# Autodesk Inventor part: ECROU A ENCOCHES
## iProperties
Created: 2004-11
Part Number: ECROU A ENCOCHES
Document SubType Name: Modeling
Designer: Bruno
Manufacturer: Standard
Standards Organization: Custom
Author: Bruno
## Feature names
1. Base1
